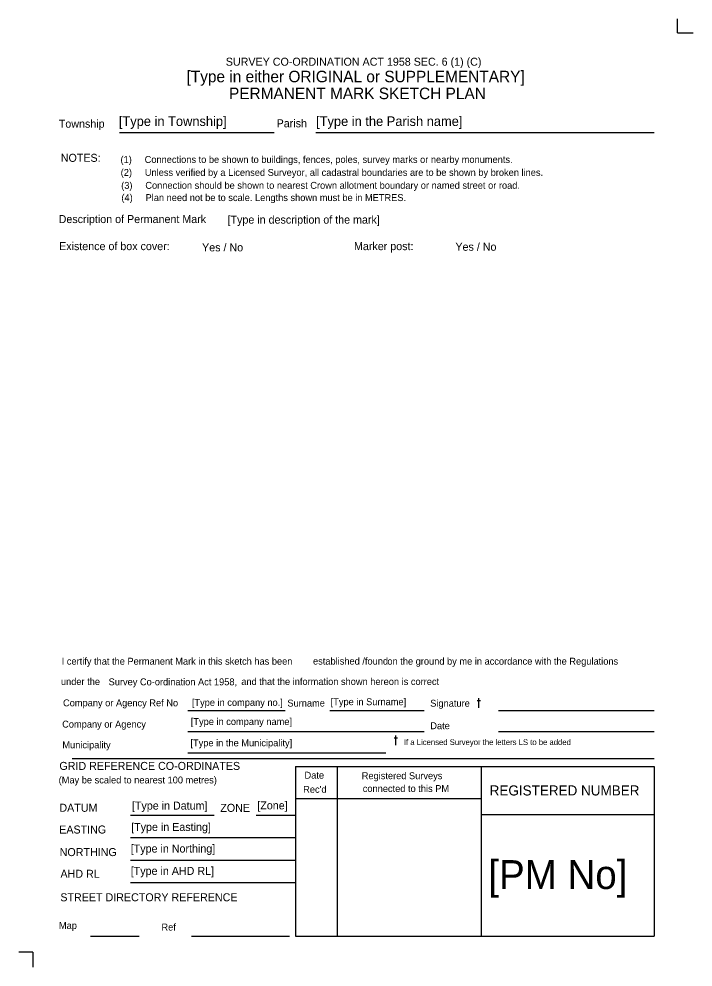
# Model space of a CAD drawing. Extents: x -4 to 206, y -5 to 291.
import ezdxf

# ---------------------------------------------------------------- set-up
doc = ezdxf.new("R2010")
doc.units = 0
for name, color, linetype in [('3', 7, 'Continuous'), ('4', 7, 'Continuous'), ('Default', 7, 'Continuous'), ('Level 40 - Proforma', 7, 'Continuous'), ('Title Block Text 2.5', 7, 'Continuous')]:
    doc.layers.add(name, color=color, linetype=linetype)

msp = doc.modelspace()

# ---------------------------------------------------------------- linework, layer by layer
at = {"layer": '3'}
for p, q in [((82.12, 58), (194.12, 58)), ((82.12, 58), (82.12, 5)), ((95.12, 58), (95.12, 5)), ((140.12, 58), (140.12, 5)), ((194.12, 58), (194.12, 5)), ((82.12, 48), (140.12, 48)), ((140.12, 43), (194.12, 43)), ((82.12, 5), (194.12, 5))]:
    msp.add_line(p, q, dxfattribs=at)
at = {"layer": '4'}
for p, q in [((27.13, 255.93), (75.46, 255.93)), ((88.48, 255.93), (194.12, 255.93)), ((48.41, 75.52), (78.85, 75.52)), ((92.78, 75.52), (122.26, 75.52)), ((145.49, 75.52), (194.12, 75.52)), ((48.41, 68.96), (122.26, 68.96)), ((145.49, 68.96), (194.12, 68.96)), ((48.41, 62.24), (110.36, 62.24)), ((12.29, 60.5), (194.12, 60.5)), ((30.56, 42.79), (56.65, 42.79)), ((69.82, 42.79), (82.12, 42.79)), ((30.56, 35.79), (82.12, 35.79)), ((30.56, 28.79), (82.12, 28.79)), ((30.56, 21.79), (82.12, 21.79)), ((17.99, 5), (33.26, 5)), ((49.63, 5), (80.18, 5))]:
    msp.add_line(p, q, dxfattribs=at)
at = {"layer": 'Default'}
for p, q in [((201.49, 287.07), (201.49, 291.42)), ((201.49, 287.07), (206.3, 287.07)), ((0, 0), (-4.32, 0)), ((0, 0), (0, -4.63))]:
    msp.add_line(p, q, dxfattribs=at)
at = {"layer": 'Title Block Text 2.5'}
for p, q in [((138.85, 78.55), (139.9, 78.55)), ((139.32, 76.26), (139.32, 79.33)), ((112.94, 66.92), (113.99, 66.92)), ((113.41, 64.63), (113.41, 67.7))]:
    msp.add_line(p, q, dxfattribs=at)

# ---------------------------------------------------------------- texts
at = {"layer": '3'}
for s, height, p in [('SURVEY CO-ORDINATION ACT 1958 SEC. 6 (1) (C)', 2.5, (60.31, 276.82)), ('Township', 2.5, (8.13, 257.46)), ('Parish', 2.5, (76.19, 257.59)), ('NOTES: ', 2.5, (8.75, 246.81)), (' (1)     Connections to be shown to buildings, fences, poles, survey marks or nearby monuments.', 2.16, (26.61, 246.46)), ('(2)     Unless verified by a Licensed Surveyor, all cadastral boundaries are to be shown by broken lines.', 2.16, (27.47, 242.42)), ('(3)     Connection should be shown to nearest Crown allotment boundary or named street or road.', 2.16, (27.62, 238.38)), ('(4)     Plan need not be to scale. Lengths shown must be in METRES.', 2.16, (27.69, 234.55)), ('Description of Permanent Mark ', 2.5, (8.08, 227.68)), ('Existence of box cover:                                                              Marker post:        ', 2.5, (8.22, 219.23)), ('I certify that the Permanent Mark in this sketch has been                                     on the ground by me in accordance with the Regulations ', 2.16, (9.03, 89.78)), ('established /found', 2.16, (87.56, 89.82)), ('under the                                                       and that the information shown hereon is correct                ', 2.16, (8.8, 83.44)), ('Survey Co-ordination Act 1958,', 2.16, (23.69, 83.34)), ('Company or Agency Ref No', 2.16, (9.45, 76.78)), ('Surname', 2.16, (79.55, 76.71)), ('Signature', 2.16, (124.18, 76.66)), ('Company or Agency', 2.16, (9.18, 70.13)), ('Date', 2.16, (124.2, 69.64)), ('Municipality', 2.16, (9.24, 63.67)), ('If a Licensed Surveyor the letters LS to be added', 1.8, (115.95, 64.69)), ('GRID REFERENCE CO-ORDINATES', 2.5, (8.31, 56.92)), ('Date', 2.16, (84.91, 54.19)), ('Registered Surveys', 2.16, (102.78, 54.03)), ('(May be scaled to nearest 100 metres)', 2.16, (8.08, 52.7)), ("Rec'd", 2.16, (84.49, 49.77)), ('connected to this PM', 2.16, (103.1, 50.02)), ('DATUM', 2.5, (8.31, 43.85)), ('ZONE', 2.5, (58.59, 43.83)), ('EASTING', 2.5, (8.26, 37.06)), ('NORTHING', 2.5, (8.4, 30.01)), ('AHD RL', 2.5, (8.65, 23.24)), ('STREET DIRECTORY REFERENCE ', 2.5, (8.61, 15.9)), ('Map', 2.16, (8.17, 7.26)), ('Ref', 2.16, (40.2, 6.75))]:
    msp.add_text(s, height=height, dxfattribs=at).set_placement(p)
at = {"layer": '4'}
for s, height, p in [('[Type in either ORIGINAL or SUPPLEMENTARY]', 3.6, (48.03, 271.65)), ('PERMANENT MARK SKETCH PLAN', 3.6, (61.3, 266.38)), ('REGISTERED NUMBER', 3.15, (142.75, 48.94))]:
    msp.add_text(s, height=height, dxfattribs=at).set_placement(p)
at = {"layer": 'Default'}
for s, p in [('[Type in Datum]', (30.98, 44.53)), ('[Zone]', (70.15, 44.6)), ('[Type in Easting]', (30.74, 37.86)), ('[Type in Northing]', (30.61, 31.12)), ('[Type in AHD RL]', (30.61, 24.14))]:
    msp.add_text(s, height=2.5, dxfattribs=at).set_placement(p)
at = {"layer": 'Level 40 - Proforma'}
for s, height, p in [('[Type in Township]', 3, (26.89, 258)), ('[Type in the Parish name]', 3, (88.52, 258)), ('[Type in description of the mark]', 2.5, (60.86, 227.51)), ('Yes / No', 2.5, (52.9, 218.85)), ('Yes / No', 2.5, (132.05, 219.04)), ('[Type in company no.]', 2.16, (49.7, 76.92)), ('[Type in Surname]', 2.16, (93.07, 77.13)), ('[Type in company name]', 2.16, (49.37, 70.93)), ('[Type in the Municipality]', 2.16, (49.26, 64.29)), ('[PM No]', 9, (142.33, 19.74))]:
    msp.add_text(s, height=height, dxfattribs=at).set_placement(p)

doc.saveas('drawing.dxf')
